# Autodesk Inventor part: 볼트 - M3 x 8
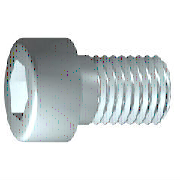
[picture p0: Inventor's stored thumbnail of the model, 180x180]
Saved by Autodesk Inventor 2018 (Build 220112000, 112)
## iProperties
IsCustomPart: 0
Created: 2012-02
Part Number: 볼트 - M3 x 8
Material: 스테인리스강
Description: 6각 소켓 머리 캡 나사
Document SubType Name: Modeling
Standard: ISO 4762
Designer: mduedu
Standard Revision: Fourth edition 2004-03-01
Standards Organization: ISO
Language: ko-KR
Size Designation: M3 x 8
Categories: <MemberInstance><Categories><Category DisplayName="조임쇠" InternalName="e4da775c-781d-43d5-af7c-5136215cf5a6" Mnemonic="FSTN"><Category DisplayName="볼트" InternalN
Density: 8.08 g/cm^3
Mass: 0.955869 g
Surface Area: 1.83001 cm^2
Volume: 0.118301 cm^3
Appearance: 반광택
Author: mduedu
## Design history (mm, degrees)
sketch "스케치1"
  geometry: L1 (-0.867, 0)-(8, 0); L2 (8, 0)-(8, 1.5); L3 (8, 1.5)-(1.25, 1.5); L4 (1.25, 1.5)-(0.943, 1.5); L5 (0.943, 1.5)-(0, 1.5); L6 (0, 1.5)-(0, 2.75); L7 (0, 2.75)-(-3, 2.75); L8 (-3, 2.75)-(-3, 1.443); L9 (-3, 1.443)-(-1.7, 1.443); L10 (-1.7, 1.443)-(-0.867, 0); L11 (-5.2, 0)-(10.2, 0) reference; L12 (0, -0.55)-(0, 3.3) reference; L13 (1.25, 1.5)-(0, 1.5)
  constraints: 22 end point, 6 parallel, 2 collinear, 2 perpendicular, 1 horizontal, 1 point on line
  dimensions: "d1" = 6.75 distance from line of L3.end L2 (= GEL); "d2" = 0.30683 distance of L4.end L3.end (computed from GAL); "d3" = 3 distance between parallel lines of L8 L6 (= KOH); "d4" = 1.3 distance of L8.end L9.end (= INTI); "d5" = 60 deg angle of L10 L1; "d6" = 3 diameter of L3 L1 (= GD); "d7" = 3 diameter of L5 L1 (= BDM); "d8" = 2.88675 diameter of L9 L1 (= 1.1547 x SW); "d9" = 5.5 diameter of L7 L1 (= KOD); "d26" = 8 distance between parallel lines of L12 L2 (= NLG)
revolve "본체" sketch "스케치1" stored, may be unused: angle "d10" = 90 deg
sketch "스케치2"
  geometry: L1 (0, -3.85)-(0, 3.85) reference; L2 (-3.85, 0)-(3.85, 0) reference; L3 (1.443, 0)-(0.722, -1.25); L4 (0.722, -1.25)-(-0.722, -1.25); L5 (-0.722, -1.25)-(-1.443, 0); L6 (-1.443, 0)-(-0.722, 1.25); L7 (-0.722, 1.25)-(0.722, 1.25); L8 (0.722, 1.25)-(1.443, 0); 2 further points
  constraints: 12 end point, 1 coincident, 1 horizontal alignment, 1 point on line, 12 other
extrude "슬롯" join sketch "스케치2" stored distance "d11" = 10; taper "d12" = 0 deg
workplane "Work Plane1"
fillet "Fillet2" dims "d30" = 0.1 (= R)
body "Solid1"
fillet "모깎기1" dims "d17" = 0.3 (= RR)
feature "스레드" dims "d13" = 6.75 (= GEL), "d14" = 0
chamfer "모따기1" distance "d15" = 0.30673 (= -0.5 x SPD + 0.5 x GD); stored, may be unused: second distance "d16" = 0.30673 (= GUL), angle "d27" = 45 deg
other parameters: "GD" = 3 [user parameter; used in 2 equation terms], "NLG" = 8 [user parameter; used in 1 equation term], "GEL" = 6.75 [user parameter; used in 2 equation terms], "KOD" = 5.5 [user parameter; used in 1 equation term], "KOH" = 3 [user parameter; used in 1 equation term], "INTI" = 1.3 [user parameter; used in 1 equation term], "GAL" = 0.30673 (= 0.61345 x PTC) [user parameter; used in 1 equation term], "GUL" = 0.30673 (= 0.61345 x PTC) [user parameter; used in 1 equation term], "BDM" = 3 (= NND) [user parameter; used in 1 equation term], "SW" = 2.5 [user parameter; used in 2 equation terms], "RR" = 0.3 [user parameter; used in 1 equation term], "SPD" = 2.38655 (= NND - 1.2269 x PTC) [user parameter; used in 1 equation term], "d19" = 0, "d28" = 0, "d29" = 0, "R" = 0.1 [user parameter; used in 1 equation term], "TOA" = 30 deg [user parameter], "GD1" = 2.38655 (= THREADDIA - 1.2269 x PTC) [user parameter], "THREADDIA" = 3 [user parameter; used in 1 equation term], "FAWI" = 45 deg [user parameter], "PTC" = 0.5 [user parameter; used in 5 equation terms], "NND" = 3 [user parameter; used in 2 equation terms], "E0" = 2.8875 (= 1.155 x SW) [user parameter]
